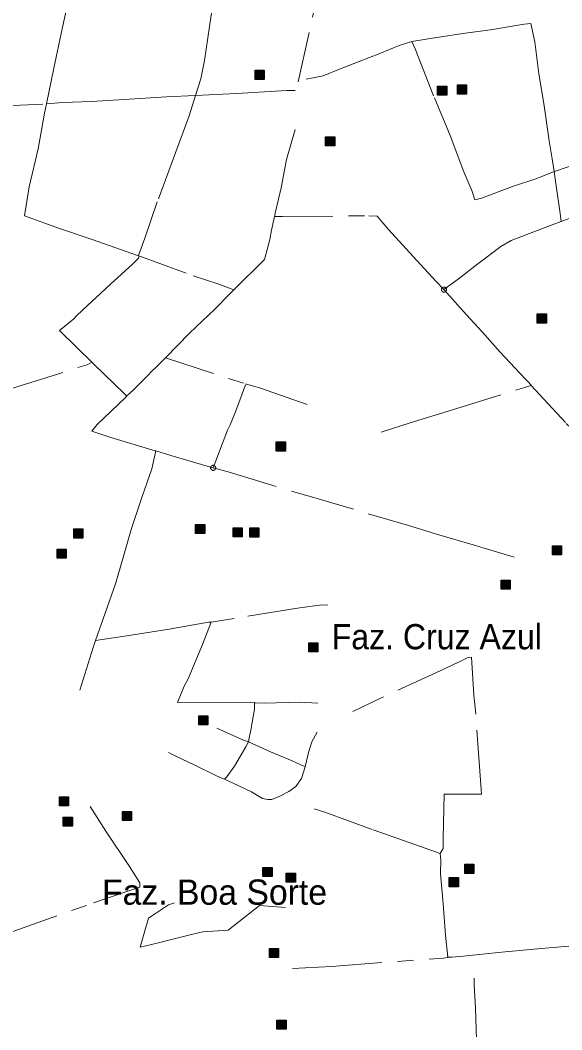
# Model space of a CAD drawing. Extents: x 393.5 to 446.9, y 8064.8 to 8120.4.
# Drawn here: x 412.88 to 416.31, y 8075.67 to 8082.08 of the extents above; entities that cross this region are included whole.
import ezdxf

# ---------------------------------------------------------------- set-up
doc = ezdxf.new("R2010")
doc.units = 0
doc.header["$LTSCALE"] = 0.064
doc.header["$PDMODE"] = 32
doc.header["$PDSIZE"] = 0.032
doc.linetypes.add('DOT_DASHED', pattern=[7.7, 5, -1.2, 0.3, -1.2])
doc.layers.add('2', color=7, linetype='Continuous', lineweight=25)
doc.layers.add('22', color=7, linetype='DOT_DASHED', lineweight=13)
doc.layers.add('61', color=7, linetype='Continuous')

msp = doc.modelspace()

# ---------------------------------------------------------------- hatches: boundary and pattern name
at = {"layer": '2'}
for points in [[(414.3689, 8081.7609), (414.4269, 8081.7609), (414.4269, 8081.7029), (414.3689, 8081.7029)], [(415.5254, 8081.6602), (415.5834, 8081.6602), (415.5834, 8081.6022), (415.5254, 8081.6022)], [(415.6513, 8081.6672), (415.7093, 8081.6672), (415.7093, 8081.6092), (415.6513, 8081.6092)], [(414.8153, 8081.3388), (414.8733, 8081.3388), (414.8733, 8081.2808), (414.8153, 8081.2808)], [(416.1576, 8080.2149), (416.2156, 8080.2149), (416.2156, 8080.1569), (416.1576, 8080.1569)], [(414.5024, 8079.4025), (414.5604, 8079.4025), (414.5604, 8079.3445), (414.5024, 8079.3445)], [(413.9918, 8078.8789), (414.0498, 8078.8789), (414.0498, 8078.8209), (413.9918, 8078.8209)], [(413.2188, 8078.8504), (413.2768, 8078.8504), (413.2768, 8078.7924), (413.2188, 8078.7924)], [(414.2296, 8078.8572), (414.2876, 8078.8572), (414.2876, 8078.7992), (414.2296, 8078.7992)], [(414.3344, 8078.8569), (414.3924, 8078.8569), (414.3924, 8078.7989), (414.3344, 8078.7989)], [(416.2544, 8078.7432), (416.3124, 8078.7432), (416.3124, 8078.6852), (416.2544, 8078.6852)], [(413.1133, 8078.722), (413.1713, 8078.722), (413.1713, 8078.664), (413.1133, 8078.664)], [(415.9287, 8078.526), (415.9867, 8078.526), (415.9867, 8078.468), (415.9287, 8078.468)], [(414.7088, 8078.1285), (414.7668, 8078.1285), (414.7668, 8078.0705), (414.7088, 8078.0705)], [(414.0116, 8077.6644), (414.0696, 8077.6644), (414.0696, 8077.6064), (414.0116, 8077.6064)], [(413.1281, 8077.1513), (413.1861, 8077.1513), (413.1861, 8077.0933), (413.1281, 8077.0933)], [(413.1519, 8077.0218), (413.2099, 8077.0218), (413.2099, 8076.9638), (413.1519, 8076.9638)], [(413.5277, 8077.0574), (413.5857, 8077.0574), (413.5857, 8076.9994), (413.5277, 8076.9994)], [(414.418, 8076.7023), (414.476, 8076.7023), (414.476, 8076.6443), (414.418, 8076.6443)], [(415.6975, 8076.7222), (415.7555, 8076.7222), (415.7555, 8076.6642), (415.6975, 8076.6642)], [(414.5666, 8076.667), (414.6246, 8076.667), (414.6246, 8076.609), (414.5666, 8076.609)], [(415.5996, 8076.6382), (415.6576, 8076.6382), (415.6576, 8076.5802), (415.5996, 8076.5802)], [(414.4596, 8076.1891), (414.5176, 8076.1891), (414.5176, 8076.1311), (414.4596, 8076.1311)], [(414.5071, 8075.7333), (414.5651, 8075.7333), (414.5651, 8075.6753), (414.5071, 8075.6753)]]:
    msp.add_hatch(color=256, dxfattribs=at).paths.add_polyline_path(points)

# ---------------------------------------------------------------- linework, layer by layer
for points in [[(414.3689, 8081.7609), (414.4269, 8081.7609), (414.4269, 8081.7029), (414.3689, 8081.7029)], [(415.5254, 8081.6602), (415.5834, 8081.6602), (415.5834, 8081.6022), (415.5254, 8081.6022)], [(415.6513, 8081.6672), (415.7093, 8081.6672), (415.7093, 8081.6092), (415.6513, 8081.6092)], [(414.8153, 8081.3388), (414.8733, 8081.3388), (414.8733, 8081.2808), (414.8153, 8081.2808)], [(416.1576, 8080.2149), (416.2156, 8080.2149), (416.2156, 8080.1569), (416.1576, 8080.1569)], [(414.5024, 8079.4025), (414.5604, 8079.4025), (414.5604, 8079.3445), (414.5024, 8079.3445)], [(413.9918, 8078.8789), (414.0498, 8078.8789), (414.0498, 8078.8209), (413.9918, 8078.8209)], [(413.2188, 8078.8504), (413.2768, 8078.8504), (413.2768, 8078.7924), (413.2188, 8078.7924)], [(414.2296, 8078.8572), (414.2876, 8078.8572), (414.2876, 8078.7992), (414.2296, 8078.7992)], [(414.3344, 8078.8569), (414.3924, 8078.8569), (414.3924, 8078.7989), (414.3344, 8078.7989)], [(416.2544, 8078.7432), (416.3124, 8078.7432), (416.3124, 8078.6852), (416.2544, 8078.6852)], [(413.1133, 8078.722), (413.1713, 8078.722), (413.1713, 8078.664), (413.1133, 8078.664)], [(415.9287, 8078.526), (415.9867, 8078.526), (415.9867, 8078.468), (415.9287, 8078.468)], [(414.7088, 8078.1285), (414.7668, 8078.1285), (414.7668, 8078.0705), (414.7088, 8078.0705)], [(414.0116, 8077.6644), (414.0696, 8077.6644), (414.0696, 8077.6064), (414.0116, 8077.6064)], [(413.1281, 8077.1513), (413.1861, 8077.1513), (413.1861, 8077.0933), (413.1281, 8077.0933)], [(413.1519, 8077.0218), (413.2099, 8077.0218), (413.2099, 8076.9638), (413.1519, 8076.9638)], [(413.5277, 8077.0574), (413.5857, 8077.0574), (413.5857, 8076.9994), (413.5277, 8076.9994)], [(414.418, 8076.7023), (414.476, 8076.7023), (414.476, 8076.6443), (414.418, 8076.6443)], [(415.6975, 8076.7222), (415.7555, 8076.7222), (415.7555, 8076.6642), (415.6975, 8076.6642)], [(414.5666, 8076.667), (414.6246, 8076.667), (414.6246, 8076.609), (414.5666, 8076.609)], [(415.5996, 8076.6382), (415.6576, 8076.6382), (415.6576, 8076.5802), (415.5996, 8076.5802)], [(414.4596, 8076.1891), (414.5176, 8076.1891), (414.5176, 8076.1311), (414.4596, 8076.1311)], [(414.5071, 8075.7333), (414.5651, 8075.7333), (414.5651, 8075.6753), (414.5071, 8075.6753)]]:
    msp.add_lwpolyline(points, close=True, dxfattribs=at)
at = {"layer": '22'}
for p, q in [((415.5616, 8080.3673), (415.5609, 8080.3667)), ((413.8008, 8079.9361), (414.3074, 8079.7702)), ((413.7385, 8079.3454), (413.7358, 8079.3462)), ((414.1028, 8079.238), (414.103, 8079.238))]:
    msp.add_line(p, q, dxfattribs=at)
for points in [[(413.0453, 8081.5475), (413.093, 8081.7739), (413.1449, 8082.0238), (413.1829, 8082.197), (413.2552, 8082.5826), (413.2952, 8082.7586), (413.3795, 8083.1593), (413.393, 8083.2438)], [(413.9911, 8081.6012), (414.0242, 8081.7069), (414.0474, 8081.8219), (414.0892, 8082.1093), (414.1217, 8082.2892), (414.1495, 8082.4445), (414.2153, 8082.8203)], [(414.6415, 8081.6873), (414.7848, 8082.3314), (414.8, 8082.3884), (414.8022, 8082.4211)], [(415.3633, 8081.9423), (415.4537, 8081.957), (415.6856, 8081.9945), (415.8623, 8082.0176), (416.0746, 8082.0533), (416.1174, 8082.0569), (416.1424, 8081.941)], [(415.3633, 8081.9423), (415.2821, 8081.9168), (415.159, 8081.8669), (415.0287, 8081.8152), (414.9038, 8081.767), (414.8004, 8081.726), (414.7379, 8081.7118), (414.6933, 8081.7046)], [(415.3633, 8081.9423), (415.3634, 8081.9421), (415.3845, 8081.8971), (415.5058, 8081.5851)], [(416.1424, 8081.941), (416.1674, 8081.7378), (416.1995, 8081.5506), (416.2334, 8081.3135), (416.2513, 8081.1994), (416.2659, 8081.1186), (416.2662, 8081.1172)], [(413.9911, 8081.6012), (414.2501, 8081.6135), (414.5729, 8081.6324), (414.6219, 8081.6327)], [(413.0453, 8081.5475), (413.1497, 8081.555), (413.3314, 8081.5631), (413.5386, 8081.576)], [(413.5386, 8081.576), (413.8073, 8081.5924), (413.9911, 8081.6012)], [(413.9911, 8081.6012), (413.9502, 8081.4707), (413.867, 8081.2439), (413.7483, 8080.9255), (413.6696, 8080.6944), (413.6324, 8080.5912), (413.629, 8080.5832)], [(415.5058, 8081.5851), (415.6057, 8081.3463), (415.6915, 8081.1162), (415.7433, 8080.9985), (415.7629, 8080.9379), (415.8039, 8080.9486), (416.0002, 8081.0235), (416.1554, 8081.0734), (416.2654, 8081.1184), (416.2659, 8081.1186)], [(412.472, 8081.5208), (412.7032, 8081.5317), (413.0453, 8081.5475)], [(413.0453, 8081.5475), (413.0329, 8081.4889), (412.993, 8081.261), (412.9369, 8081.0218), (412.9069, 8080.8361), (413.1282, 8080.7556), (413.3355, 8080.6871), (413.629, 8080.5832)], [(414.6223, 8081.3849), (414.5679, 8081.1953), (414.5342, 8081.014), (414.4963, 8080.8538), (414.4942, 8080.8441), (414.4929, 8080.8336)], [(416.5141, 8081.2027), (416.3536, 8081.1475), (416.2662, 8081.1172)], [(416.3096, 8080.8013), (416.3022, 8080.8507), (416.2777, 8081.0274), (416.2696, 8081.0859), (416.2659, 8081.1186)], [(416.636, 8080.9259), (416.5231, 8080.883), (416.3096, 8080.8013)], [(414.2344, 8080.3672), (414.2362, 8080.3689), (414.4287, 8080.5593), (414.4627, 8080.6871), (414.4731, 8080.7466), (414.4926, 8080.8321), (414.4929, 8080.8336)], [(414.4929, 8080.8336), (414.5415, 8080.8336), (415.0907, 8080.837), (415.1433, 8080.8349), (415.2142, 8080.7504), (415.3275, 8080.6275), (415.4182, 8080.5273), (415.5185, 8080.4173), (415.5635, 8080.3717), (415.5662, 8080.3689), (415.6018, 8080.3285)], [(416.3096, 8080.8013), (416.2519, 8080.7793), (415.9913, 8080.6796), (415.926, 8080.6433), (415.7813, 8080.5319), (415.6552, 8080.4352), (415.5662, 8080.3689)], [(413.2363, 8080.2031), (413.2742, 8080.2377), (413.45, 8080.4022), (413.5908, 8080.5312), (413.6303, 8080.5683), (413.6328, 8080.5819)], [(413.629, 8080.5832), (413.6314, 8080.5824), (413.975, 8080.4567), (414.132, 8080.405), (414.2344, 8080.3672)], [(413.8008, 8079.9361), (413.9531, 8080.0915), (414.1134, 8080.2449), (414.204, 8080.3371), (414.2344, 8080.3672)], [(415.6018, 8080.3285), (415.6892, 8080.2298), (415.7318, 8080.1827)], [(413.34, 8079.9015), (413.1281, 8080.1098), (413.2203, 8080.1842), (413.2363, 8080.2031)], [(415.7318, 8080.1827), (415.8075, 8080.1016), (415.9224, 8079.9722), (416.0794, 8079.8057), (416.0987, 8079.7868), (416.1187, 8079.7621), (416.1197, 8079.7609)], [(412.6688, 8079.6918), (412.8452, 8079.7468), (413.3033, 8079.8923), (413.3327, 8079.9089)], [(413.34, 8079.9015), (413.348, 8079.8935), (413.538, 8079.71), (413.5527, 8079.6938), (413.5541, 8079.6923), (413.5542, 8079.6922)], [(413.8008, 8079.9361), (413.7509, 8079.8852), (413.7093, 8079.8461)], [(413.7093, 8079.8461), (413.6901, 8079.8264), (413.5978, 8079.7326), (413.573, 8079.709), (413.5542, 8079.6922)], [(414.2103, 8079.5099), (414.244, 8079.5929), (414.3078, 8079.7644)], [(414.3074, 8079.7702), (414.4028, 8079.7435), (414.6981, 8079.6406)], [(415.1673, 8079.4639), (415.351, 8079.5231), (415.6201, 8079.6069), (416.076, 8079.748), (416.1197, 8079.7609)], [(416.1197, 8079.7609), (416.3411, 8079.5194), (416.3737, 8079.49)], [(413.7358, 8079.3462), (413.4539, 8079.4296), (413.3341, 8079.4698), (413.3678, 8079.5138), (413.5471, 8079.6844), (413.5542, 8079.6922)], [(414.1028, 8079.238), (414.1928, 8079.4765), (414.2103, 8079.5099)], [(413.3566, 8078.1414), (413.4175, 8078.315), (413.4831, 8078.5011), (413.5329, 8078.6695), (413.5829, 8078.847), (413.6505, 8079.0491), (413.7141, 8079.2307), (413.7385, 8079.3454)], [(413.7385, 8079.3454), (413.8343, 8079.3171), (414.1004, 8079.2387), (414.1028, 8079.238)], [(414.103, 8079.238), (414.1971, 8079.2132), (414.6502, 8079.0741), (414.7554, 8079.045), (414.7692, 8079.0422), (414.9936, 8078.9763)], [(415.0858, 8078.9464), (415.3345, 8078.8745), (415.4508, 8078.8375), (415.5195, 8078.8164), (415.7662, 8078.7442), (415.8209, 8078.7283), (416.0112, 8078.6702)], [(414.8293, 8078.3676), (414.7908, 8078.3681), (414.6377, 8078.3467), (414.237, 8078.2822), (414.0907, 8078.2594)], [(413.3566, 8078.1414), (413.5823, 8078.1766), (413.8237, 8078.2153), (414.0739, 8078.2593), (414.0907, 8078.2594)], [(413.9451, 8077.8994), (414.0343, 8078.1177), (414.0907, 8078.2594)], [(413.3566, 8078.1414), (413.3414, 8078.0979), (413.2578, 8077.8277)], [(415.5426, 8076.7899), (415.5602, 8076.8216), (415.5602, 8076.8868), (415.567, 8077.168), (415.8051, 8077.1681), (415.7988, 8077.2553), (415.7675, 8077.6778), (415.7562, 8077.7963), (415.7412, 8078.0364), (415.7131, 8078.0328), (415.6655, 8078.0064), (415.6304, 8077.9922)], [(415.6304, 8077.9922), (415.5645, 8077.961), (415.1551, 8077.7727), (414.9877, 8077.6917)], [(414.3648, 8077.7481), (414.185, 8077.7516), (413.8758, 8077.748), (413.9198, 8077.8518), (413.9451, 8077.8994)], [(414.3648, 8077.7481), (414.3648, 8077.7059), (414.3416, 8077.5738), (414.3337, 8077.5347), (414.3264, 8077.4985)], [(414.7665, 8077.7458), (414.652, 8077.7516), (414.4282, 8077.7446), (414.3688, 8077.7479), (414.3648, 8077.7481)], [(414.1255, 8077.5865), (414.2947, 8077.5108), (414.3264, 8077.4985)], [(414.6851, 8077.3413), (414.6874, 8077.3486), (414.7071, 8077.4308), (414.7281, 8077.5), (414.7621, 8077.5608)], [(414.3264, 8077.4985), (414.3105, 8077.4686), (414.2372, 8077.3448), (414.1896, 8077.2775), (414.1749, 8077.2631)], [(414.6851, 8077.3413), (414.6027, 8077.3784), (414.467, 8077.4365), (414.3264, 8077.4985)], [(413.819, 8077.4321), (413.8665, 8077.4075), (413.9864, 8077.3511), (414.1238, 8077.2842), (414.1685, 8077.2657), (414.1749, 8077.2631)], [(414.6851, 8077.3413), (414.6619, 8077.2664), (414.6264, 8077.2155), (414.582, 8077.1839), (414.5256, 8077.1557), (414.4745, 8077.1346), (414.4498, 8077.1328), (414.4146, 8077.1398), (414.3459, 8077.1821), (414.2648, 8077.2208), (414.1749, 8077.2631)], [(412.5043, 8076.1872), (412.528, 8076.1922), (412.594, 8076.2159), (412.6786, 8076.2447), (412.8095, 8076.2886), (413.3443, 8076.4776), (413.5626, 8076.552), (413.6371, 8076.5774), (413.6371, 8076.6044), (413.5728, 8076.7076), (413.4213, 8076.9325), (413.3233, 8077.0882)], [(414.7426, 8077.0734), (414.8113, 8077.054), (415.1179, 8076.9414), (415.4175, 8076.8357), (415.5426, 8076.7899)], [(415.5914, 8076.1327), (415.5757, 8076.2736), (415.5607, 8076.4725), (415.5448, 8076.6627), (415.5461, 8076.7494), (415.5426, 8076.7899)], [(413.8569, 8076.4786), (413.8201, 8076.4646), (413.6921, 8076.3804), (413.6645, 8076.2853), (413.6399, 8076.1971), (413.7481, 8076.2214), (413.8381, 8076.2457), (413.9644, 8076.278), (414.038, 8076.2942), (414.1986, 8076.3052), (414.3968, 8076.4612), (414.5617, 8076.4489)], [(416.3575, 8076.204), (416.1594, 8076.1855), (415.9091, 8076.1638), (415.6893, 8076.1404), (415.6155, 8076.1328), (415.5914, 8076.1327)], [(414.6063, 8076.0619), (414.8537, 8076.0746), (415.5626, 8076.1275), (415.5866, 8076.1318), (415.5888, 8076.1322), (415.5914, 8076.1327)], [(415.7849, 8075.2864), (415.7841, 8075.3082), (415.7768, 8075.4406), (415.775, 8075.5431), (415.7657, 8075.8097), (415.7584, 8075.9578), (415.7584, 8076.0003)]]:
    msp.add_lwpolyline(points, dxfattribs=at)
for p in [(415.5662, 8080.3689), (414.1028, 8079.238)]:
    msp.add_point(p, dxfattribs=at)

# ---------------------------------------------------------------- texts
at = {"layer": '61', "width": 0.95}
msp.add_text('Faz. Cruz Azul', height=0.16, dxfattribs=at).set_placement((414.8542, 8078.0867))
at = {"layer": '61'}
msp.add_text('Faz. Boa Sorte', height=0.16, dxfattribs=at).set_placement((413.398, 8076.4659))

doc.saveas('drawing.dxf')
